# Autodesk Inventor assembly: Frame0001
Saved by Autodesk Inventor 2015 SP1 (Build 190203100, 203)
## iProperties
Created: 2011-06
Part Number: Frame0001
Document SubType Name: Assembly
Designer: Guilherme Augusto Franco de Souza
Engineer: George Geraldo de Oliveia Silva
Authority: Fábio Ricardo de Oliveira Soza
_FrameDoc: Frame Assembly
_Version: 15.0.0
Category: Mechanical Engineering Drawing and Design - CADD
Manager: Fábio Ricardo de Oliveira Souza
Company: SENAI - Serviço Nacional de Aprendizagem Industrial
Subject: WorldSkill 2011 - London, England
Author: Guilherme Augusto Franco de Souza
Revision Number: 00
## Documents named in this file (24)
- E:\Visitor Experience Project\WSI2015 - Visitor Experience Project\#46- Sheet Metal Technology\01- 3D Models\Outodoor Heater\2- Assemblies\Frame\Frame\Frame0001.iam
- E:\Visitor Experience Project\WSI2015 - Visitor Experience Project\#46- Sheet Metal Technology\01- 3D Models\Outodoor Heater\2- Assemblies\Frame\Frame\Skeleton0001.ipt
- E:\Visitor Experience Project\WSI2015 - Visitor Experience Project\#46- Sheet Metal Technology\01- 3D Models\Outodoor Heater\2- Assemblies\Frame\Frame\ISO 25x25x2 00000001.ipt
- ISO 25x25x2 00000001.ipt
- E:\Visitor Experience Project\WSI2015 - Visitor Experience Project\#46- Sheet Metal Technology\01- 3D Models\Outodoor Heater\2- Assemblies\Frame\Frame\ISO 25x25x2 00000002.ipt
- ISO 25x25x2 00000002.ipt
- E:\Visitor Experience Project\WSI2015 - Visitor Experience Project\#46- Sheet Metal Technology\01- 3D Models\Outodoor Heater\2- Assemblies\Frame\Frame\ISO 25x25x2 00000003.ipt
- ISO 25x25x2 00000003.ipt
- E:\Visitor Experience Project\WSI2015 - Visitor Experience Project\#46- Sheet Metal Technology\01- 3D Models\Outodoor Heater\2- Assemblies\Frame\Frame\ISO 25x25x2 00000004.ipt
- ISO 25x25x2 00000004.ipt
- E:\Visitor Experience Project\WSI2015 - Visitor Experience Project\#46- Sheet Metal Technology\01- 3D Models\Outodoor Heater\2- Assemblies\Frame\Frame\ISO 25x25x2 00000005.ipt
- ISO 25x25x2 00000005.ipt
- E:\Visitor Experience Project\WSI2015 - Visitor Experience Project\#46- Sheet Metal Technology\01- 3D Models\Outodoor Heater\2- Assemblies\Frame\Frame\ISO 25x25x2 00000006.ipt
- ISO 25x25x2 00000006.ipt
- E:\Visitor Experience Project\WSI2015 - Visitor Experience Project\#46- Sheet Metal Technology\01- 3D Models\Outodoor Heater\2- Assemblies\Frame\Frame\ISO 25x25x2 00000007.ipt
- ISO 25x25x2 00000007.ipt
- E:\Visitor Experience Project\WSI2015 - Visitor Experience Project\#46- Sheet Metal Technology\01- 3D Models\Outodoor Heater\2- Assemblies\Frame\Frame\ISO 25x25x2 00000008.ipt
- ISO 25x25x2 00000008.ipt
- E:\Visitor Experience Project\WSI2015 - Visitor Experience Project\#46- Sheet Metal Technology\01- 3D Models\Outodoor Heater\2- Assemblies\Frame\Frame\ISO 25x25x2 00000009.ipt
- ISO 25x25x2 00000009.ipt
- E:\Visitor Experience Project\WSI2015 - Visitor Experience Project\#46- Sheet Metal Technology\01- 3D Models\Outodoor Heater\2- Assemblies\Frame\Frame\ISO 25x25x2 00000010.ipt
- ISO 25x25x2 00000010.ipt
- E:\Visitor Experience Project\WSI2015 - Visitor Experience Project\#46- Sheet Metal Technology\01- 3D Models\Outodoor Heater\2- Assemblies\Frame\Frame\ISO 25x25x2 00000011.ipt
- ISO 25x25x2 00000011.ipt
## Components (12 placed, 12 different names)
1. Frame Reference Model
2. ISO 25x25x2 00000001:1
3. ISO 25x25x2 00000002:1
4. ISO 25x25x2 00000003:1
5. ISO 25x25x2 00000004:1
6. ISO 25x25x2 00000005:1
7. ISO 25x25x2 00000006:1
8. ISO 25x25x2 00000007:1
9. ISO 25x25x2 00000008:1
10. ISO 25x25x2 00000009:1
11. ISO 25x25x2 00000010:1
12. ISO 25x25x2 00000011:1
